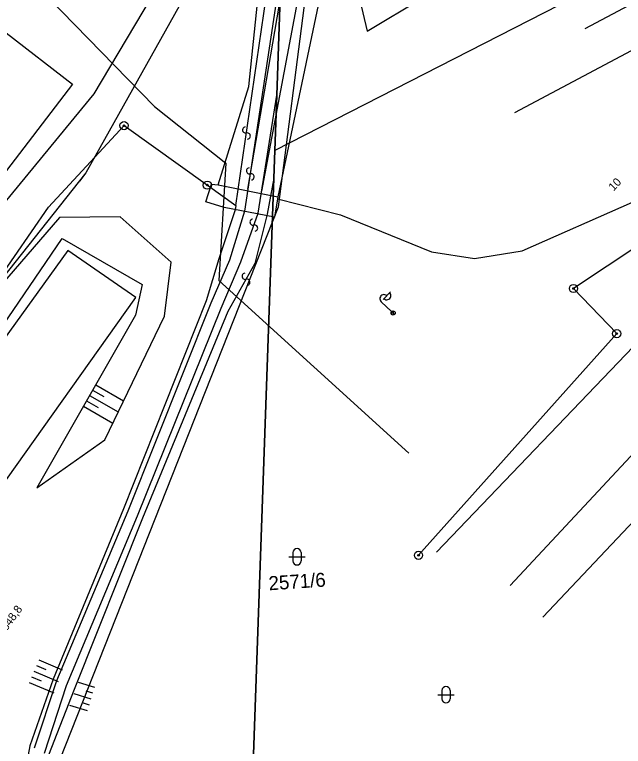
# Model space of a CAD drawing. Extents: x -469926 to -462499, y -1098642 to -1092733.
# Drawn here: x -465664.7 to -465590.7, y -1095836.3 to -1095747.3 of the extents above; entities that cross this region are included whole.
import ezdxf

# ---------------------------------------------------------------- set-up
doc = ezdxf.new("R2010")
doc.units = 0
for name, color, linetype in [('Vrstva 1', 7, 'Continuous'), ('Vrstva 13', 7, 'Continuous'), ('Vrstva 24', 7, 'Continuous'), ('Vrstva 25', 7, 'Continuous'), ('Vrstva 29', 7, 'Continuous'), ('Vrstva 4', 7, 'Continuous'), ('Vrstva 48', 7, 'Continuous'), ('Vrstva 50', 7, 'Continuous'), ('Vrstva 51', 7, 'Continuous'), ('Vrstva 55', 7, 'Continuous'), ('Vrstva 6', 7, 'Continuous')]:
    doc.layers.add(name, color=color, linetype=linetype)

msp = doc.modelspace()

# ---------------------------------------------------------------- linework, layer by layer
at = {"layer": 'Vrstva 1'}
for p, q in [((-465580.68, -1095737.04), (-465633.05, -1095763.85)), ((-465665.74, -1095749.55), (-465657.68, -1095755.79)), ((-465657.68, -1095755.79), (-465681.9, -1095787.32)), ((-465660.56, -1095770.74), (-465651.39, -1095760.81)), ((-465651.39, -1095760.81), (-465641.26, -1095768.05)), ((-465576.88, -1095767.42), (-465596.72, -1095780.62)), ((-465641.26, -1095768.05), (-465637.78, -1095770.54)), ((-465613.4, -1095812.69), (-465572.57, -1095770.04)), ((-465685.14, -1095806.16), (-465660.56, -1095770.74)), ((-465637.86, -1095771.07), (-465639.85, -1095777.01)), ((-465637.78, -1095770.54), (-465637.86, -1095771.07)), ((-465639.85, -1095777.01), (-465641.41, -1095782.12)), ((-465596.72, -1095780.62), (-465591.46, -1095786.11)), ((-465641.41, -1095782.12), (-465651.46, -1095807.43)), ((-465591.46, -1095786.11), (-465615.57, -1095813.06)), ((-465651.46, -1095807.43), (-465660.03, -1095828.11)), ((-465660.03, -1095828.11), (-465662.87, -1095836.24)), ((-465662.87, -1095836.24), (-465664.05, -1095843.01))]:
    msp.add_line(p, q, dxfattribs=at)
for points in [[(-465568.43, -1095778.129), (-465604.44, -1095816.733)], [(-465600.444, -1095820.584), (-465564.23, -1095782.265)]]:
    msp.add_lwpolyline(points, dxfattribs=at)
at = {"layer": 'Vrstva 13'}
for p, q in [((-465632.26, -1095741.6), (-465632.81, -1095757.13)), ((-465632.81, -1095757.13), (-465632.26, -1095741.6)), ((-465633.17, -1095767.19), (-465632.81, -1095757.13)), ((-465632.81, -1095757.13), (-465633.05, -1095763.85)), ((-465633.05, -1095763.85), (-465633.17, -1095767.19)), ((-465633.17, -1095767.19), (-465635.74, -1095839.92)), ((-465635.74, -1095839.92), (-465633.17, -1095767.19))]:
    msp.add_line(p, q, dxfattribs=at)
at = {"layer": 'Vrstva 24'}
for centre, radius in [((-465651.39, -1095760.81), 0.5), ((-465651.39, -1095760.81), 0.1), ((-465641.26, -1095768.05), 0.5), ((-465641.26, -1095768.05), 0.1), ((-465596.72, -1095780.62), 0.5), ((-465596.72, -1095780.62), 0.1), ((-465591.46, -1095786.11), 0.5), ((-465591.46, -1095786.11), 0.1), ((-465615.57, -1095813.06), 0.5), ((-465615.57, -1095813.06), 0.1)]:
    msp.add_circle(centre, radius, dxfattribs=at)
at = {"layer": 'Vrstva 25'}
for p, q in [((-465612.73, -1095829.51), (-465612.73, -1095830.51)), ((-465611.73, -1095829.51), (-465611.73, -1095830.51)), ((-465613.23, -1095830.01), (-465611.23, -1095830.01))]:
    msp.add_line(p, q, dxfattribs=at)
for centre, start, end in [((-465612.231, -1095829.511), 0, 180), ((-465612.231, -1095830.511), 180, 0)]:
    msp.add_arc(centre, 0.5, start, end, dxfattribs=at)
at = {"layer": 'Vrstva 29'}
for p, q in [((-465630.85, -1095812.74), (-465630.85, -1095813.74)), ((-465629.85, -1095812.74), (-465629.85, -1095813.74)), ((-465631.35, -1095813.24), (-465629.35, -1095813.24))]:
    msp.add_line(p, q, dxfattribs=at)
for centre, start, end in [((-465630.351, -1095812.741), 0, 180), ((-465630.351, -1095813.741), 180, 0)]:
    msp.add_arc(centre, 0.5, start, end, dxfattribs=at)
at = {"layer": 'Vrstva 4'}
for p, q in [((-465637.78, -1095770.54), (-465632.69, -1095735.39)), ((-465632.26, -1095741.6), (-465636.72, -1095771.22)), ((-465635.09, -1095771.44), (-465632.81, -1095757.13)), ((-465633.17, -1095767.19), (-465634, -1095771.58)), ((-465636.72, -1095771.22), (-465638.56, -1095777.18)), ((-465637.17, -1095777.36), (-465635.09, -1095771.44)), ((-465634, -1095771.58), (-465635.49, -1095777.59)), ((-465638.56, -1095777.18), (-465640.83, -1095782.4)), ((-465639.57, -1095783.01), (-465637.17, -1095777.36)), ((-465635.49, -1095777.59), (-465638.76, -1095783.41)), ((-465640.83, -1095782.4), (-465650.92, -1095807.69)), ((-465649.75, -1095808.26), (-465639.57, -1095783.01)), ((-465638.76, -1095783.41), (-465649.16, -1095808.54)), ((-465650.92, -1095807.69), (-465659.62, -1095828.31)), ((-465658.41, -1095828.9), (-465649.75, -1095808.26)), ((-465649.16, -1095808.54), (-465657.46, -1095829.36)), ((-465659.62, -1095828.31), (-465662.33, -1095836.5)), ((-465661.07, -1095837.11), (-465658.41, -1095828.9)), ((-465657.46, -1095829.36), (-465660.58, -1095837.36))]:
    msp.add_line(p, q, dxfattribs=at)
at = {"layer": 'Vrstva 48'}
for points in [[(-465654.84, -1095792.329), (-465651.438, -1095794.268)], [(-465655.212, -1095792.981), (-465653.833, -1095793.766)], [(-465655.955, -1095794.284), (-465654.541, -1095795.09)], [(-465655.583, -1095793.632), (-465652.092, -1095795.622)], [(-465656.326, -1095794.935), (-465652.747, -1095796.976)], [(-465661.759, -1095825.762), (-465658.902, -1095826.98)], [(-465662.348, -1095827.142), (-465659.422, -1095828.389)], [(-465662.053, -1095826.452), (-465660.897, -1095826.945)], [(-465662.642, -1095827.832), (-465661.458, -1095828.336)], [(-465662.936, -1095828.522), (-465659.941, -1095829.798)], [(-465654.949, -1095829.119), (-465656.949, -1095828.509)], [(-465655.387, -1095830.554), (-465657.46, -1095829.922)], [(-465655.168, -1095829.837), (-465655.983, -1095829.588)], [(-465655.825, -1095831.989), (-465657.971, -1095831.334)], [(-465655.606, -1095831.271), (-465656.45, -1095831.014)]]:
    msp.add_lwpolyline(points, dxfattribs=at)
at = {"layer": 'Vrstva 51'}
for p, q in [((-465667.126, -1095738.521), (-465647.689, -1095758.491)), ((-465647.689, -1095758.491), (-465639.009, -1095765.386)), ((-465639.009, -1095765.386), (-465639.849, -1095779.658)), ((-465639.849, -1095779.658), (-465616.768, -1095800.646))]:
    msp.add_line(p, q, dxfattribs=at)
for centre, radius, start, end in [((-465636.595, -1095761.346), 0.376, 98.10036, 284.41149), ((-465636.403, -1095762.074), 0.377, 277.42432, 105.08753), ((-465636.131, -1095766.32), 0.376, 98.10036, 284.41149), ((-465635.939, -1095767.048), 0.377, 277.42432, 105.08753), ((-465635.699, -1095772.543), 0.376, 98.10036, 284.41149), ((-465635.508, -1095773.271), 0.377, 277.42432, 105.08753), ((-465636.657, -1095779.136), 0.376, 98.10036, 284.41149), ((-465636.465, -1095779.864), 0.377, 277.42432, 105.08753)]:
    msp.add_arc(centre, radius, start, end, dxfattribs=at)
at = {"layer": 'Vrstva 55'}
for p, q in [((-465655.039, -1095756.941), (-465631.989, -1095718.363)), ((-465678.326, -1095785.306), (-465655.039, -1095756.941)), ((-465658.22, -1095775.995), (-465682.737, -1095809.952)), ((-465649.975, -1095781.698), (-465658.22, -1095775.995)), ((-465619.88, -1095781.966), (-465618.989, -1095781.02)), ((-465673.921, -1095815.424), (-465649.975, -1095781.698)), ((-465618.845, -1095783.42), (-465620.12, -1095782.221)), ((-465618.774, -1095783.816), (-465618.787, -1095783.376)), ((-465618.586, -1095783.829), (-465618.6, -1095783.35))]:
    msp.add_line(p, q, dxfattribs=at)
for points in [[(-465613.129, -1095700), (-465626.347, -1095715.087), (-465635.019, -1095729.016), (-465656.052, -1095766.543), (-465669.35, -1095783.31)], [(-465613.129, -1095700), (-465626.347, -1095715.087), (-465635.019, -1095729.016), (-465656.052, -1095766.543), (-465656.825, -1095767.572)], [(-465639.962, -1095768.013), (-465636.216, -1095756.069), (-465634.086, -1095735.656), (-465631.502, -1095725.782), (-465622.299, -1095713.967), (-465612.075, -1095704.018), (-465605.98, -1095700)], [(-465600.97, -1095700), (-465612.483, -1095708.211), (-465620.399, -1095714.883), (-465629.694, -1095727.391), (-465631.846, -1095735.803), (-465632.561, -1095746.29), (-465636.383, -1095768.552)], [(-465634.635, -1095768.783), (-465630.306, -1095745.782), (-465628.06, -1095730.905), (-465623.313, -1095721.394), (-465615.402, -1095713.373), (-465604.375, -1095705.867), (-465597.617, -1095700.001)], [(-465593.595, -1095700), (-465601.669, -1095708.032), (-465614.198, -1095717.194), (-465620.251, -1095722.537), (-465623.188, -1095728.444), (-465625.828, -1095736.875), (-465632.69, -1095769.493)], [(-465492.952, -1095699.999), (-465527.919, -1095718.658), (-465573.619, -1095743.118), (-465603.884, -1095759.271)], [(-465595.305, -1095748.995), (-465574.579, -1095737.991), (-465539.251, -1095719.039), (-465503.4, -1095700)], [(-465582.536, -1095720.45), (-465596.103, -1095724.052), (-465610.306, -1095728.279), (-465617.367, -1095737.132), (-465622.88, -1095744.821), (-465621.818, -1095749.314), (-465594.75, -1095733.062), (-465581.713, -1095726.229), (-465582.536, -1095720.45)], [(-465632.725, -1095769.702), (-465625.071, -1095771.675), (-465614.002, -1095776.17), (-465608.763, -1095776.952), (-465602.985, -1095776.026), (-465589.547, -1095770.105), (-465586.022, -1095766.947), (-465583.214, -1095762.239), (-465583.941, -1095761.524), (-465576.007, -1095756.627), (-465579.031, -1095749.035), (-465579.871, -1095732.202)], [(-465639.198, -1095770.775), (-465641.439, -1095770.067), (-465640.771, -1095767.917), (-465639.962, -1095768.013), (-465632.69, -1095769.493), (-465633.105, -1095771.948), (-465639.198, -1095770.775)], [(-465670.795, -1095791.914), (-465658.924, -1095774.53), (-465649.191, -1095780.139), (-465650.003, -1095783.842), (-465661.979, -1095804.853), (-465653.734, -1095799.021), (-465646.477, -1095783.996), (-465645.658, -1095777.401), (-465651.854, -1095771.905), (-465659.226, -1095771.987), (-465665.63, -1095779.421), (-465671.878, -1095791.154), (-465670.795, -1095791.914)]]:
    msp.add_lwpolyline(points, dxfattribs=at)
msp.add_circle((-465618.663, -1095783.592), 0.25, dxfattribs=at)
msp.add_circle((-465618.663, -1095783.592), 0.25, dxfattribs=at)
for centre, start, end in [((-465619.777, -1095781.857), 46.74368, 226.74368), ((-465619.43, -1095781.497), 226.04111, 47.44625)]:
    msp.add_arc(centre, 0.5, start, end, dxfattribs=at)
at = {"layer": 'Vrstva 6'}
for p, q in [((-465632.609, -1095770.687), (-465628.692, -1095740.391)), ((-465659.149, -1095837.842), (-465632.609, -1095770.687))]:
    msp.add_line(p, q, dxfattribs=at)

# ---------------------------------------------------------------- texts
at = {"layer": 'Vrstva 50'}
msp.add_text('2571/6', height=1.7, rotation=3.843, dxfattribs=at).set_placement((-465633.754, -1095817.323))
at = {"layer": 'Vrstva 55'}
for s, rotation, p in [('10', 46.29718, (-465591.853, -1095768.832)), ('348,8', 54.09889, (-465665.666, -1095822.316))]:
    msp.add_text(s, height=1, rotation=rotation, dxfattribs=at).set_placement(p)

doc.saveas('drawing.dxf')
